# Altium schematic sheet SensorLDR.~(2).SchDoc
size A
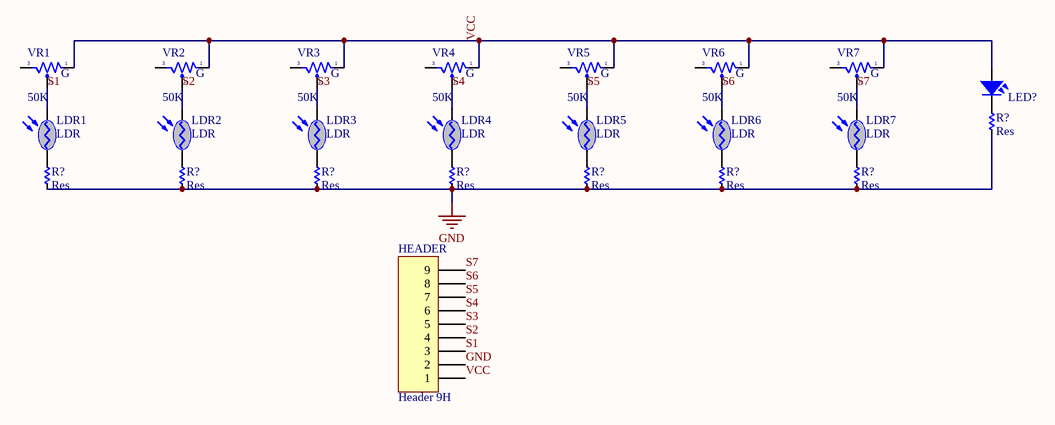
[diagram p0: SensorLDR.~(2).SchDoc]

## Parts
(Parts that share a designator on the sheet are numbered #1, #2 ... from top to bottom, then left to right.)
HEADER  Header 9H  [HDR1X9H]
LDR1  LDR  [CDS]
LDR2  LDR  [CDS]
LDR3  LDR  [CDS]
LDR4  LDR  [CDS]
LDR5  LDR  [CDS]
LDR6  LDR  [CDS]
LDR7  LDR  [CDS]
LED?  LED  [LED-3MM-YELLOW]  (value not drawn)
R?#1  Res  [RES-1/2W]
R?#2  Res  [RES-1/2W]
R?#3  Res  [RES-1/2W]
R?#4  Res  [RES-1/2W]
R?#5  Res  [RES-1/2W]
R?#6  Res  [RES-1/2W]
R?#7  Res  [RES-1/2W]
R?#8  Res  [RES-1/2W]
VR1  50K  [VR-S1]
VR2  50K  [VR-S1]
VR3  50K  [VR-S1]
VR4  50K  [VR-S1]
VR5  50K  [VR-S1]
VR6  50K  [VR-S1]
VR7  50K  [VR-S1]

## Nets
GND: HEADER.2 R?#1.2 R?#2.2 R?#3.2 R?#4.2 R?#5.2 R?#6.2 R?#7.2 R?#8.2
S1: HEADER.3 LDR1.2(K) VR1.2
S2: HEADER.4 LDR2.2(K) VR2.2
S3: HEADER.5 LDR3.2(K) VR3.2
S4: HEADER.6 LDR4.2(K) VR4.2
S5: HEADER.7 LDR5.2(K) VR5.2
S6: HEADER.8 LDR6.2(K) VR6.2
S7: HEADER.9 LDR7.2(K) VR7.2
VCC: HEADER.1 LED?.1 VR1.1 VR2.1 VR3.1 VR4.1 VR5.1 VR6.1 VR7.1
NetLDR1_1: LDR1.1(A) R?#2.1
NetLDR2_1: LDR2.1(A) R?#3.1
NetLDR3_1: LDR3.1(A) R?#4.1
NetLDR4_1: LDR4.1(A) R?#5.1
NetLDR5_1: LDR5.1(A) R?#6.1
NetLDR6_1: LDR6.1(A) R?#7.1
NetLDR7_1: LDR7.1(A) R?#8.1
NetLED?_2: LED?.2 R?#1.1

Not connected (* = marked no-connect by the designer): VR1 3; VR2 3; VR3 3; VR4 3; VR5 3; VR6 3; VR7 3

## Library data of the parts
HEADER = Header 9H: Header, 9-Pin, Right Angle
LDR1-LDR7 = LDR: Quang Tro
LED? = LED: LED Single colour Green and Red; Value: LED 3 ly Single Colour
R?#1-R?#8 = Res: Manufacturer: Generic Components; Class: Passive; SubClass: R
VR1-VR7 = VR-S: Var Resistor; Value: Volume 50k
